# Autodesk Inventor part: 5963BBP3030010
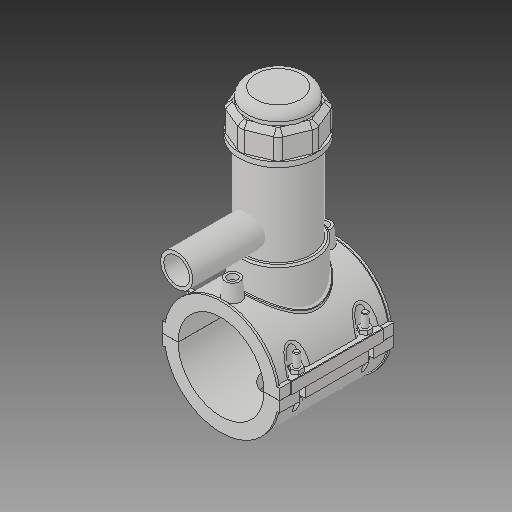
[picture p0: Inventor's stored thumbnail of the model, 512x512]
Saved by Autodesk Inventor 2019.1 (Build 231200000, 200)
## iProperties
Created: 2017-07
Part Number: 5963BBP3030010
Material: Generic
Description: PLASSON TAPPING SADDLE 3''IPS x 1''IPS
Document SubType Name: Modeling
Designer: KIM
Density: 1 g/cm^3
Appearance: Default
Author: KIM
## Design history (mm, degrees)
derived "5963BBP_5963BUP.ipt"
feature "Solid1::5963BBP_5963BUP.ipt"
feature "Solid2::5963BBP_5963BUP.ipt"
feature "Solid3::5963BBP_5963BUP.ipt"
tag "TaggingFeature1"
body "Solid1"
body "Solid2"
body "Solid3"
other parameters: "d_" = 88.7, "B_" = 120.904, "L_" = 118.11, "d_t" = 6, "H_2" = 177.038, "H_1" = 65.024, "d_1" = 33.3, "H_" = 104.902, "d1" = 115.31, "d148" = 1.3305, "d160" = 1.3305, "d169" = 3.2805, "d192" = 6.9984, "d0" = 88.7, "d2" = 120.904, "d3" = 22.175, "d4" = 118.11, "d5" = 0, "d6" = 0.1, "d8" = 0, "d19" = 6, "d20" = 6, "d21" = 70.866, "d23" = 0, "d24" = 35.433, "d26" = 0, "d27" = 3, "d28" = 3, "d29" = 3, "d30" = 29.56667, "d31" = 6, "d32" = 0, "d33" = 0, "d34" = 0.6, "d40" = 59.9612, "d41" = 79.83, "d43" = 0, "d45" = 0, "d47" = 128.521, "d70" = 15, "d72" = 0, "d73" = 6, "d75" = 5, "d76" = 0, "d77" = 4.435, "d78" = 74.35, "d79" = 15, "d80" = 47.244, "d82" = 5 deg, "d84" = 4, "d85" = 14, "d86" = 0, "d87" = 3, "d88" = 0, "d89" = 1, "d90" = 1, "d91" = 94.488, "d92" = 0, "d93" = 0.5, "d94" = 46.68421, "d96" = 117.6162, "d97" = 2.3622, "d98" = 0, "d102" = 0.887, "d120" = 140 deg, "d121" = 24.228, "d122" = 20 deg, "d123" = 230.62, "d124" = 69.186, "d126" = 0, "d143" = 91.361, "d145" = 20.46923, "d149" = 1.3305, "d150" = 22.51615, "d153" = 118.11, "d154" = 0, "d156" = 57.655, "d157" = 160 deg, "d159" = 5.322, "d161" = 1.3305, "d162" = 70.866, "d163" = 0, "d164" = 44.35, "d167" = 8.87, "d168" = 56.24878, "d170" = 3.2805, "d172" = 0, "d173" = 1, "d175" = 44.35, "d176" = 20 deg, "d177" = 6.209, "d178" = 26.61, "d180" = 0, "d183" = 10.644, "d184" = 4.9672, "d185" = 38.38575, "d186" = 38.38575, "d187" = 57.655, "d188" = 7.983, "d189" = 6.209, "d190" = 0, "d191" = 86.4825, "d193" = 6.9984, "d194" = 4.13385, "d195" = 90 deg, "d197" = 0, "d199" = 0, "d200" = 13.305, "d202" = 0, "d203" = 177.038, "d204" = 75.8385, "d205" = 55.881, "d206" = 67.8555, "d207" = 132.7785, "d208" = 138.08964, "d209" = 164.64534, "d210" = 68.6538, "d211" = 79.83, "d212" = 63.864, "d213" = 43.5366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
